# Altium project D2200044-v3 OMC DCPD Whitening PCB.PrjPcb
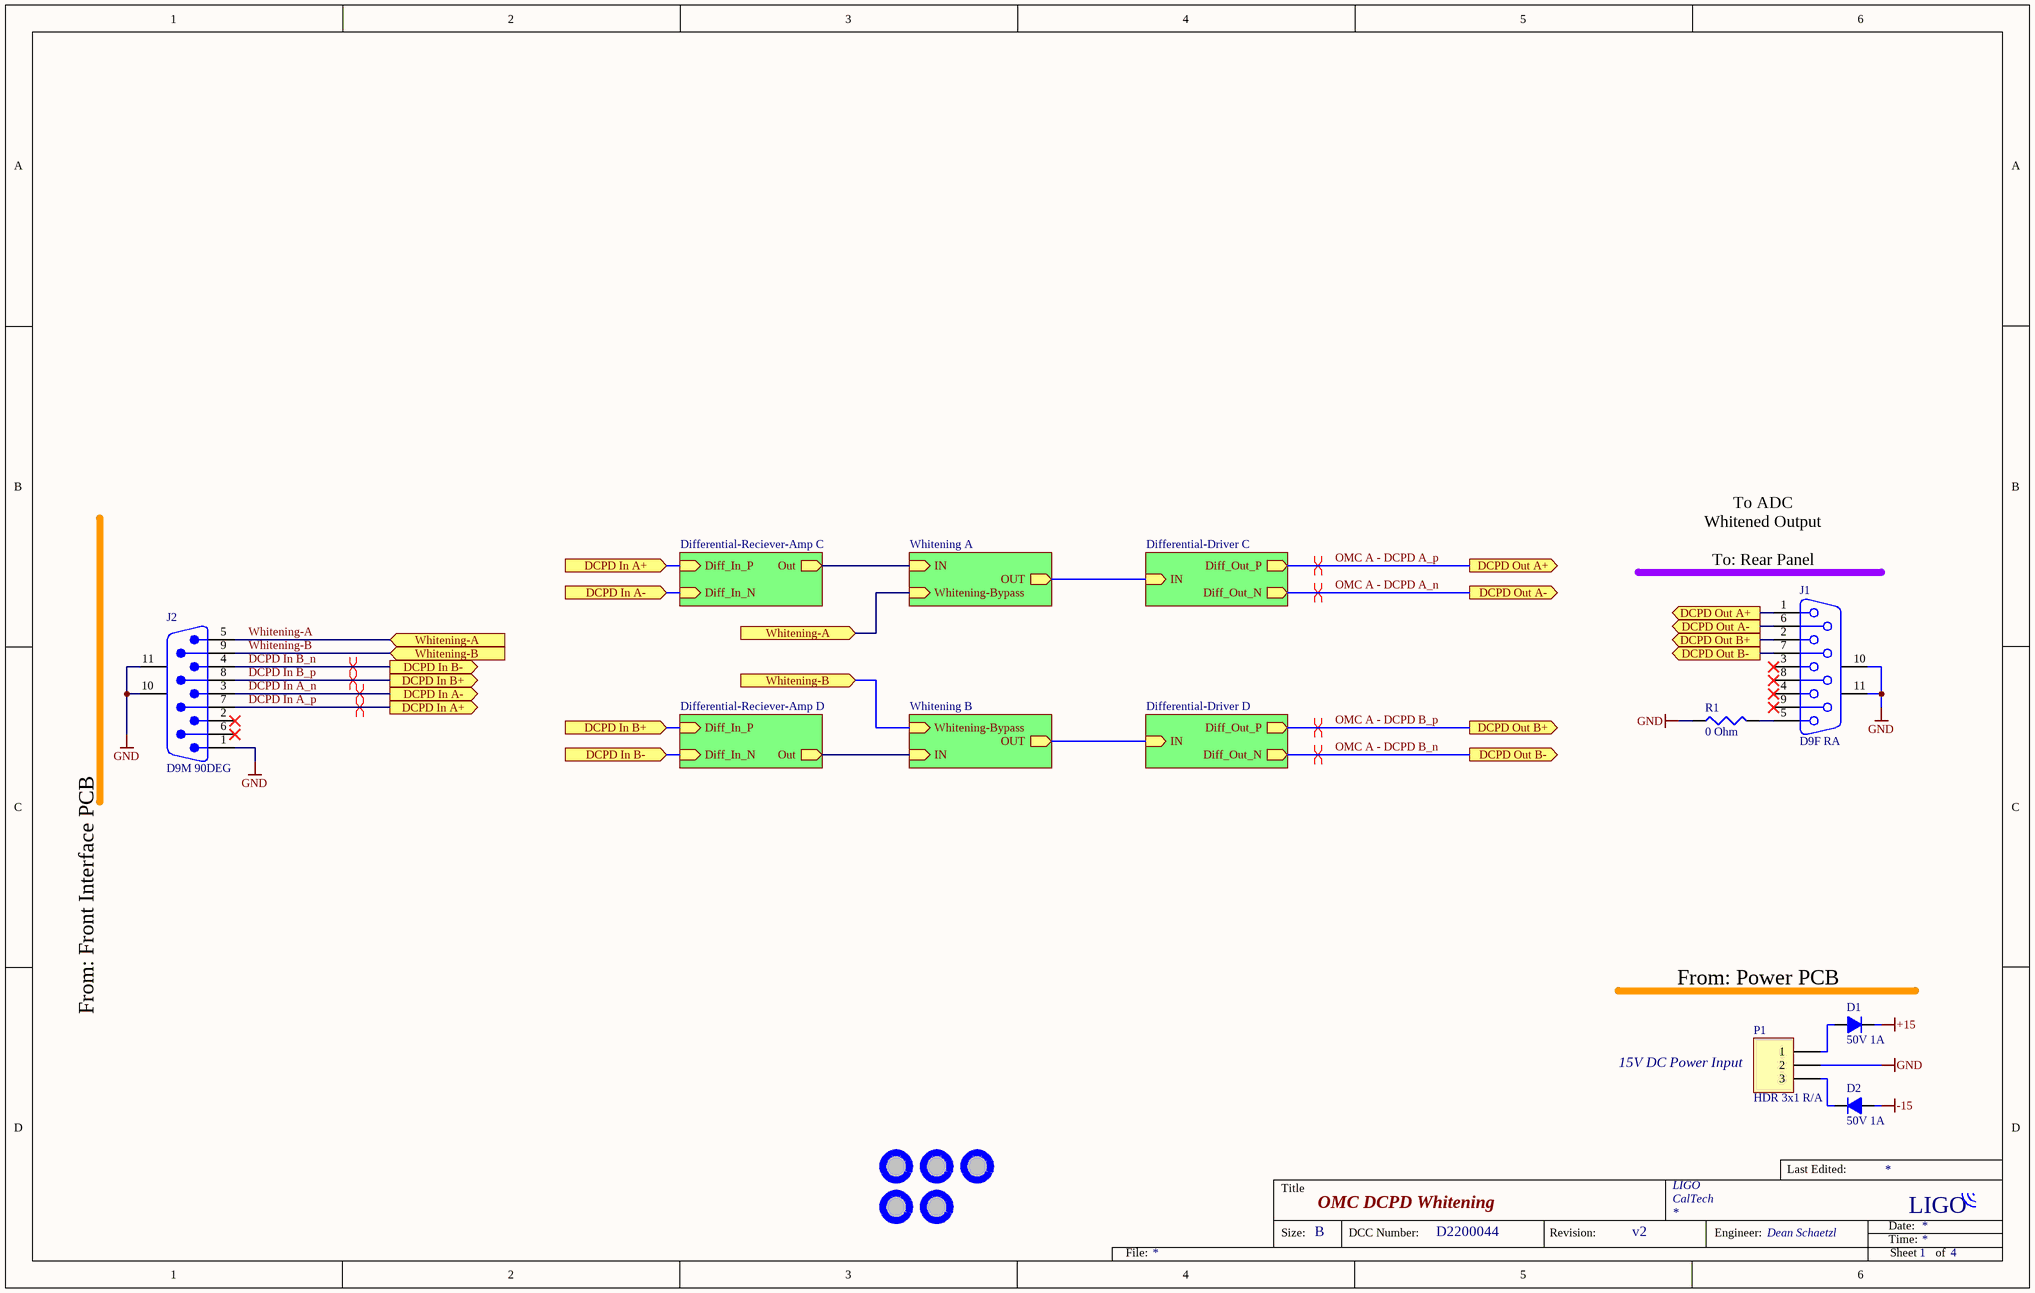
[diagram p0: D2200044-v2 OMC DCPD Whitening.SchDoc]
4 sheets, 95 parts. Net scope: hierarchical (ports join the sheet entries above them; power ports are global).
Board file: D2200044-v3 OMC DCPD Whitening PCB.PcbDoc
Sheets:
  D2200044-v2 OMC DCPD Whitening.SchDoc
    Differential-Reciever-Amp C = Differential-Reciever-Amp.SchDoc
    Differential-Driver C = Differential-Driver.SchDoc
    Differential-Reciever-Amp D = Differential-Reciever-Amp.SchDoc
    Differential-Driver D = Differential-Driver.SchDoc
    Whitening A = Whitening-v3.SchDoc
    Whitening B = Whitening-v3.SchDoc

## Sheet D2200044-v2 OMC DCPD Whitening.SchDoc: OMC DCPD Whitening
size B; CompanyName: LIGO; DrawnBy: Dean Schaetzl; Engineer: Dean Schaetzl; Organization: LIGO; Address1: CalTech; DocumentNumber: D2200044; Revision: v2; SheetNumber: 1; SheetTotal: 4

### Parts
D1  50V 1A  [DO-214AA, SMB]
D2  50V 1A  [DO-214AA, SMB]
J1  D9F RA  [D9F 90DEG]
J2  D9M 90DEG  [D9M 90DEG]
MH1  Mounting Hole #6  [Mounting Hole #6]  (value not drawn)
MH2  Mounting Hole #6  [Mounting Hole #6]  (value not drawn)
MH3  Mounting Hole #6  [Mounting Hole #6]  (value not drawn)
MH4  Mounting Hole #6  [Mounting Hole #6]  (value not drawn)
MH5  Mounting Hole #6  [Mounting Hole #6]  (value not drawn)
P1  HDR 3x1 R/A  [MOLEX HDR1X3 R/A]
R1  0 Ohm  [1206 Resistor]

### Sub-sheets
Differential-Driver C = Differential-Driver.SchDoc: Diff_Out_N (out), Diff_Out_P (out), IN (in)
Differential-Driver D = Differential-Driver.SchDoc: Diff_Out_N (out), Diff_Out_P (out), IN (in)
Differential-Reciever-Amp C = Differential-Reciever-Amp.SchDoc: Diff_In_P (in), Diff_In_N (in), Out (out)
Differential-Reciever-Amp D = Differential-Reciever-Amp.SchDoc: Diff_In_P (in), Diff_In_N (in), Out (out)
Whitening A = Whitening-v3.SchDoc: IN (in), OUT (out), Whitening-Bypass (in)
Whitening B = Whitening-v3.SchDoc: IN (in), OUT (out), Whitening-Bypass (in)

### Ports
DCPD In A+ (in), DCPD In A+ (out), DCPD In A- (in), DCPD In A- (out), DCPD In B+ (in), DCPD In B+ (out), DCPD In B- (in), DCPD In B- (out), DCPD Out A+ (out), DCPD Out A- (out), DCPD Out B+ (out), DCPD Out B- (out), Whitening-A (in), Whitening-B (in)

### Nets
+15: D1.2(K)
-15: D2.1(A)
GND: J1.10(MH1) J1.11(MH2) J2.1 J2.10(MH1) J2.11(MH2) P1.2 R1.1
DCPD In A_n: J2.3 ; port DCPD In A-, sheet Differential-Reciever-Amp C/Diff_In_N
DCPD In A_p: J2.7 ; port DCPD In A+, sheet Differential-Reciever-Amp C/Diff_In_P
DCPD In B_n: J2.4 ; port DCPD In B-, sheet Differential-Reciever-Amp D/Diff_In_N
DCPD In B_p: J2.8 ; port DCPD In B+, sheet Differential-Reciever-Amp D/Diff_In_P
OMC A - DCPD A_n: J1.6 ; port DCPD Out A-, sheet Differential-Driver C/Diff_Out_N
OMC A - DCPD A_p: J1.1 ; port DCPD Out A+, sheet Differential-Driver C/Diff_Out_P
OMC A - DCPD B_n: J1.7 ; port DCPD Out B-, sheet Differential-Driver D/Diff_Out_N
OMC A - DCPD B_p: J1.2 ; port DCPD Out B+, sheet Differential-Driver D/Diff_Out_P
Whitening-A: J2.5 ; port Whitening-A, sheet Whitening A/Whitening-Bypass
Whitening-B: J2.9 ; port Whitening-B, sheet Whitening B/Whitening-Bypass
NetC13A_2: sheet Differential-Reciever-Amp C/Out, sheet Whitening A/IN
NetC13B_2: sheet Differential-Reciever-Amp D/Out, sheet Whitening B/IN
NetD1_1: D1.1(A) P1.1
NetD2_2: D2.2(K) P1.3
NetJ1_5: J1.5 R1.2
NetK1A_8: sheet Differential-Driver C/IN, sheet Whitening A/OUT
NetK1B_8: sheet Differential-Driver D/IN, sheet Whitening B/OUT

Not connected (* = marked no-connect by the designer): J1 3* 4* 8* 9*; J2 2* 6*

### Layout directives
differential pair: DCPD In A_n, DCPD In A_p, DCPD In B_n, DCPD In B_p, OMC A - DCPD A_n, OMC A - DCPD A_p, OMC A - DCPD B_n, OMC A - DCPD B_p

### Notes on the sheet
- (near J1) To ADC
  Whitened Output
  To: Rear Panel
- From: Front Interface PCB
- (near D1) From: Power PCB
- (near P1) 15V DC Power Input

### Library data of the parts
D1 D2 = Diode 50V 1A SMB: DIODE GEN PURP 50V 1A SMB; Manufacturer: Diodes; Manufacturer Part Number: S1AB-13-F; Max Surge Current: 30A; Recovery Time: 1.8us; Forward Voltage: 1.1V; Peak Reverse Current: 5uA; Element Configuration: Single; Polarity: Standard; Capacitance: 10pF
J1 = D9F 90DEG: 9 Position D-Sub Receptacle, Female Sockets Connector; Manufacturer: TE Connectivity; Manufacturer Part Number: 5747844-4; Plating: Tin; Body Material: Metal; Voltage Rating: 125V; Current Rating: 6A; Number of Positions: 9; Number of Ports: 1; Mating Connector Lock: Yes (With); PCB Mount Retention: With; PCB Mounting Orientation: Right Angle; Preloaded: Yes; Sealable: No (Without); Pitch: 0.108inch; PCB Thickness: 1.58mm; Contact Post Length: 0.125inch; Hole Diameter: 3.18mm; Approvals: CSA,UL
J2 = D9M 90DEG: 9 Position D-Sub Plug, Male Pins Connector; Manufacturer: EDAC; Manufacturer Part Number: 621-009-260-042; Body Material: Steel; Current Rating: 5A; Connector Type: D-Sub,Plug; Number of Positions: 9
P1 = MOLEX HDR 3x1 R/A: Connector Header Through Hole, Right Angle 3 position 0.156" (3.96mm); Manufacturer: Molex; Manufacturer Part Number: 0417920512; Contact Resistance: 10mR; Number of Positions: 3; Connector Type: Male Pin
R1 = 0 Ohm (1206): RES 0 OHM JUMPER 1/4W 1206; Manufacturer: Stackpole Electronics; Manufacturer Part Number: RMCF1206ZT0R00; Current Rating: 2A; Working Voltage: 200V; Resistance: 0mR; Power Rating: 250mW

## Sheet Differential-Reciever-Amp.SchDoc: Differential Reciever Amp
size A; Engineer: Dean Schaetzl; Organization: LIGO; Address1: Caltech; DocumentNumber: D2200044; Revision: v1; SheetNumber: 3; SheetTotal: 4
Used 2 times, as channels Differential-Reciever-Amp C, Differential-Reciever-Amp D. Parts and nets are listed once, with the designators drawn on the sheet.
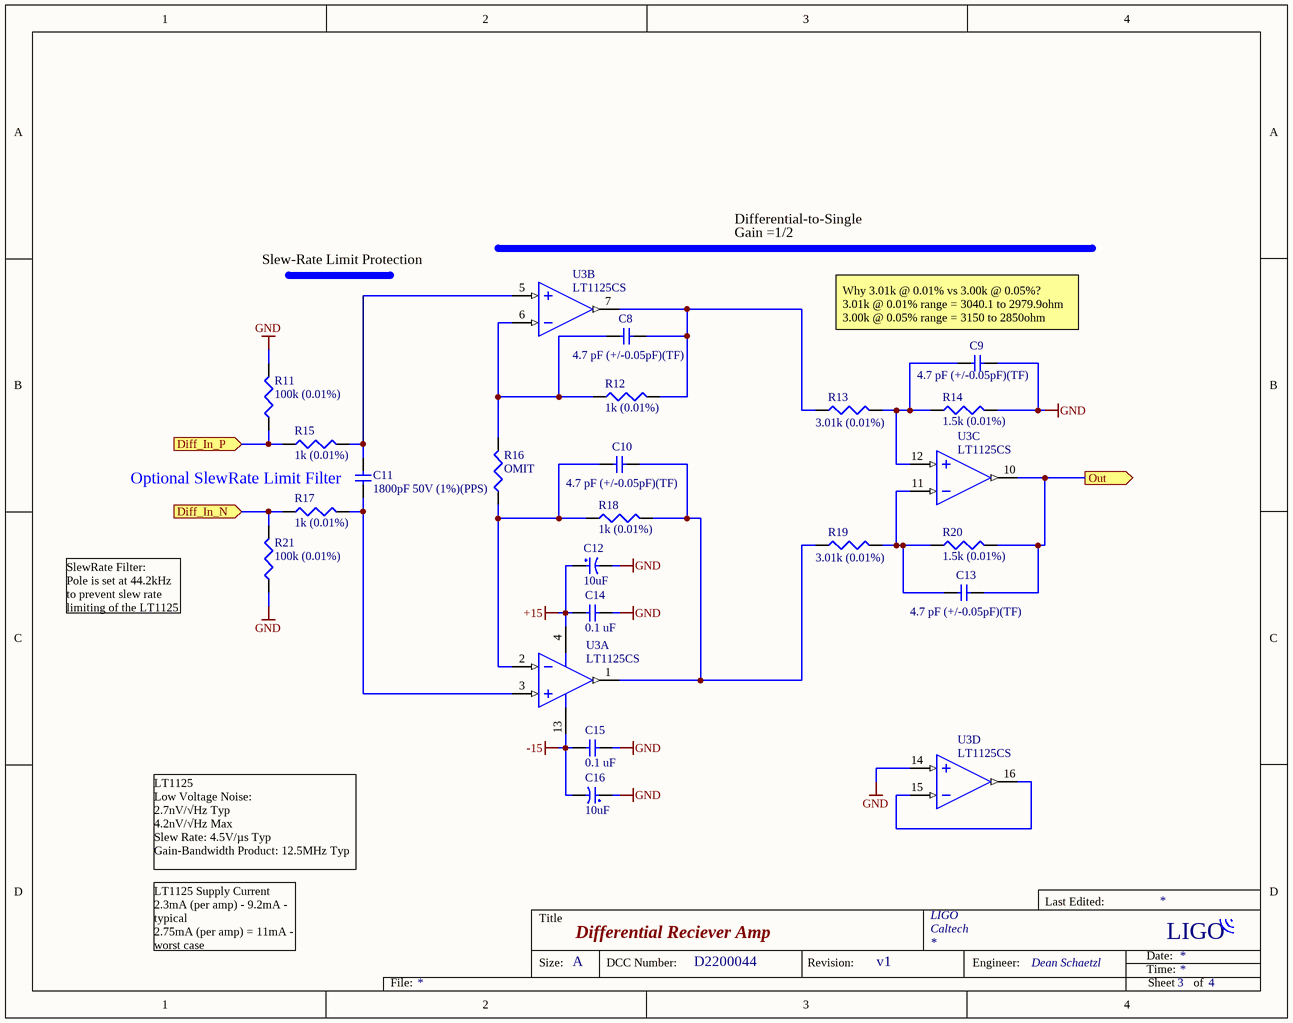
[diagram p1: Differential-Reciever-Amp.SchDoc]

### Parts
C8  4.7 pF (+/-0.05pF)(TF)  [0603 CAP]
C9  4.7 pF (+/-0.05pF)(TF)  [0603 CAP]
C10  4.7 pF (+/-0.05pF)(TF)  [0603 CAP]
C11  1800pF 50V (1%)(PPS)  [0805 CAP]
C12  10uF  [2917 (7343 Metric)]
C13  4.7 pF (+/-0.05pF)(TF)  [0603 CAP]
C14  0.1 uF  [1206 (3216 Metric) CAP]
C15  0.1 uF  [1206 (3216 Metric) CAP]
C16  10uF  [2917 (7343 Metric)]
R11  100k (0.01%)  [1206 Resistor]
R12  1k (0.01%)  [1206 Resistor]
R13  3.01k (0.01%)  [1206 Resistor]
R14  1.5k (0.01%)  [1206 Resistor]
R15  1k (0.01%)  [1206 Resistor]
R16  OMIT  [1206 Resistor - OMIT]
R17  1k (0.01%)  [1206 Resistor]
R18  1k (0.01%)  [1206 Resistor]
R19  3.01k (0.01%)  [1206 Resistor]
R20  1.5k (0.01%)  [1206 Resistor]
R21  100k (0.01%)  [1206 Resistor]
U3  LT1125CS  [SOIC-16W (0.295", 7.50mm Width)]  (parts A,B,C,D of 4)

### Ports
Diff_In_N (in), Diff_In_P (in), Out (out)

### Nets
+15: C12.1 C14.1 U3.4(V+)
-15: C15.1 C16.2 U3.13(V-)
GND: C9.2 C12.2 C14.2 C15.2 C16.1 R11.2 R14.2 R21.1 U3.14(IN+)
Diff_In_N: R17.1 R21.2 ; port Diff_In_N
Diff_In_P: R11.1 R15.1 ; port Diff_In_P
Out: C13.2 R20.2 U3.10(OUT) ; port Out
NetC8_1: C8.1 R12.1 R16.2 U3.6(IN-)
NetC8_2: C8.2 R12.2 R13.1 U3.7(OUT)
NetC9_1: C9.1 R13.2 R14.1 U3.12(IN+)
NetC10_1: C10.1 R16.1 R18.1 U3.2(IN-)
NetC10_2: C10.2 R18.2 R19.1 U3.1(OUT)
NetC11_1: C11.1 R17.2 U3.3(IN+)
NetC11_2: C11.2 R15.2 U3.5(IN+)
NetC13_1: C13.1 R19.2 R20.1 U3.11(IN-)
NetU3_15: U3.15(IN-) U3.16(OUT)

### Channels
Differential-Reciever-Amp C: designators end in A; ports Diff_In_N=DCPD In A_n Diff_In_P=DCPD In A_p Out=NetC13A_2
Differential-Reciever-Amp D: designators end in B; ports Diff_In_N=DCPD In B_n Diff_In_P=DCPD In B_p Out=NetC13B_2

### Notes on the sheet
- Differential-to-Single
- Gain =1/2
- Slew-Rate Limit Protection
- (near C9) Why 3.01k @ 0.01% vs 3.00k @ 0.05%?
  3.01k @ 0.01% range = 3040.1 to 2979.9ohm
  3.00k @ 0.05% range = 3150 to 2850ohm
- Optional SlewRate Limit Filter
- SlewRate Filter:
  Pole is set at 44.2kHz to prevent slew rate limiting of the LT1125
- LT1125
  Low Voltage Noise:
  2.7nV/√Hz Typ
  4.2nV/√Hz Max
  Slew Rate: 4.5V/µs Typ
  Gain-Bandwidth Product: 12.5MHz Typ
- LT1125 Supply Current
  2.3mA (per amp) - 9.2mA - typical
  2.75mA (per amp) = 11mA - worst case

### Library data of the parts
C8-C10 C13 = 4.7 pF +/- 0.05pF (0603): SMD Microwave Thin-Film Chip Capacitors 0603 4.7pF 50volts C0G +/-0.05pF; Manufacturer: Kyocera AVX; Manufacturer Part Number: 06035J4R7ABTTR; Voltage Rating: 50V
C11 = 1800 pF 50V 1% (0805) PPS Film: Capacitor; ECHU, SMD, Stack Met PPS Film Cap, 50VDC, 0.0018uF, 2%, 0805, Cut Tape; Manufacturer: Panasonic; Manufacturer Part Number: ECH-U1H182GX5; Dielectric Material: Polyphenylene; Capacitance: 1.8nF; Life (Hours): 500Hour; Dissipation Factor: 0.6%; Insulation Resistance: 3GR
C12 C16 = 10uF Tant 10% 35V (2917): 10µF Molded Tantalum Capacitors 35V 2917 (7343 Metric) 125mOhm; Manufacturer: KEMET; Manufacturer Part Number: T495D106K035ATE125; Polarity: Polar; Life (Hours): 2000Hour; Dissipation Factor: 6%; ESR (Equivalent Series Resistance): 125mR; Tolerance: 10%
C14 C15 = 0.1 uF 5% (1206): Multilayer Ceramic Capacitor, C Series, 0.1 - F, - 5%, C0G / NP0, 50 V, 1210 [3225 Metric] ;RoHS Compliant: Yes; Manufacturer: KEMET; Manufacturer Part Number: C1210C104J5GACTU; Capacitance: 100nF; Voltage Rating: 50V; Temperature Coefficient: 30ppm/°C; Dissipation Factor: 0.1%
R11 R21 = 100k Ohm 0.01% (1206): 100 kOhms ±0.01% 0.333W, 1/3W Chip Resistor 1206 (3216 Metric) Anti-Sulfur, Moisture Resistant Thin Film; Manufacturer: Vishay Sfernice; Manufacturer Part Number: P2TC1206D1003LNTA
R12 R15 R17 R18 = 1k Ohm 0.01% (1206): RNCF Precision Thin Film Chip Resistor 1206 Size 1K Ohm 0.01% 0.25 W 5 ppm/°C 2-Pin SMD T/R; Manufacturer: Stackpole Electronics; Manufacturer Part Number: RNCF1206TKY1K00; Resistance: 1kR; Max Power Dissipation: 250mW
R13 R19 = 3.01k Ohm 0.01% (1206): 1206 Thin Film Chip Resistor / 1206 SMD Resistor 0.05% 10PPM 3.01 Kohm; Manufacturer: Panasonic; Manufacturer Part Number: ERA-8ARW3011V; Resistance: 3.01kR; Max Power Dissipation: 250mW; Temperature Coefficient: 10ppm/°C
R14 R20 = 1.5k Ohm 0.01% (1206): Thin Film Resistors - SMD 1/4W 1.5K Ohms 0.01% 1206 2ppm; Manufacturer: Susumu; Manufacturer Part Number: RG3216L-152-L-T05; Voltage Rating: 200V; Resistance: 1.5kR; Power Rating: 250mW; Temperature Coefficient: 2ppm/°C; Max Power Dissipation: 125mW
R16 = 1206 Resistor OMIT
U3 = LT1125CS: OP Amp Quad GP ±22V 16-Pin SOIC W; Manufacturer: Analog Devices / Linear Technology; Manufacturer Part Number: LT1125CSW#PBF; Dual Supply Voltage: 9V; Number of Channels: 4; Voltage Gain: 143.52dB; Gain Bandwidth Product: 12.5MHz; Input Bias Current: 30nA; Common Mode Rejection Ratio: 106dB; Input Offset Voltage (Vos): 140uV; Operating Supply Current: 2.3mA; Slew Rate: 4.5V/µs; Power Supply Rejection Ratio (PSRR): 110dB; Min Dual Supply Voltage: 4V

## Sheet Differential-Driver.SchDoc: Differential Driver
size A; DrawnBy: Dean Schaetzl; Engineer: Dean Schaetzl; Organization: LIGO; DocumentNumber: D2200044; Revision: v1; SheetNumber: 2; SheetTotal: 4
Used 2 times, as channels Differential-Driver C, Differential-Driver D. Parts and nets are listed once, with the designators drawn on the sheet.
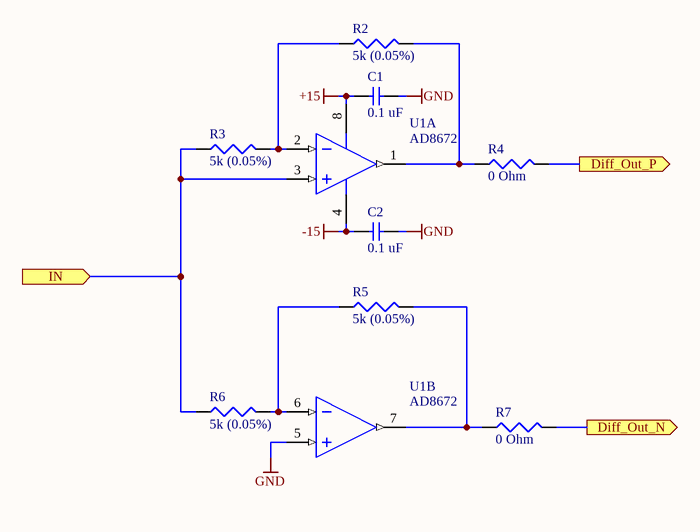
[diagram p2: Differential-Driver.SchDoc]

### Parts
C1  0.1 uF  [1206 (3216 Metric) CAP]
C2  0.1 uF  [1206 (3216 Metric) CAP]
R2  5k (0.05%)  [0805 Resistor]
R3  5k (0.05%)  [0805 Resistor]
R4  0 Ohm  [1206 Resistor]
R5  5k (0.05%)  [0805 Resistor]
R6  5k (0.05%)  [0805 Resistor]
R7  0 Ohm  [1206 Resistor]
U1  AD8672  [SOIC-8 (0.154", 3.90mm Width)]  (parts A,B of 2)

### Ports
Diff_Out_N (out), Diff_Out_P (out), IN (in)

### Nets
+15: C1.1 U1.8(V+)
-15: C2.1 U1.4(V-)
GND: C1.2 C2.2 U1.5(IN+)
Diff_Out_N: R7.2 ; port Diff_Out_N
Diff_Out_P: R4.2 ; port Diff_Out_P
IN: R3.1 R6.1 U1.3(IN+) ; port IN
NetR2_1: R2.1 R3.2 U1.2(IN-)
NetR2_2: R2.2 R4.1 U1.1(OUT)
NetR5_1: R5.1 R6.2 U1.6(IN-)
NetR5_2: R5.2 R7.1 U1.7(OUT)

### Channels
Differential-Driver C: designators end in A; ports Diff_Out_N=OMC A - DCPD A_n Diff_Out_P=OMC A - DCPD A_p IN=NetK1A_8
Differential-Driver D: designators end in B; ports Diff_Out_N=OMC A - DCPD B_n Diff_Out_P=OMC A - DCPD B_p IN=NetK1B_8

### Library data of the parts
C1 C2 = 0.1 uF 5% (1206): as C14 on sheet Differential-Reciever-Amp
R2 R3 R5 R6 = 5k Ohm 0.05% (0805): Res Thin Film 0805 5K Ohm 0.05% 1/4W ±5ppm/°C Molded SMD SMD T/R; Manufacturer: Vishay Dale Thin Film; Manufacturer Part Number: PLT0805Z5001AST5; Resistance: 5kR; Power Rating: 250mW; Voltage Rating: 100V
R4 R7 = 0 Ohm (1206): as R1 on sheet D2200044-v2 OMC DCPD Whitening
U1 = AD8672: IC OPAMP GP 10MHZ 8SOIC; Manufacturer: Analog Devices; Manufacturer Part Number: AD8672ARZ; Common Mode Rejection Ratio: 120dB; Min Supply Voltage: 10V; Max Supply Voltage: 36V; Voltage Gain: 135.56dB; Min Dual Supply Voltage: 5V; Max Dual Supply Voltage: 15V; Slew Rate: 4V/µs; Number of Channels: 2; Input Bias Current: 3nA; Input Offset Voltage (Vos): 75uV; Power Supply Rejection Ratio (PSRR): 130dB; Operating Supply Current: 7mA; Settling Time: 5.1us; Dual Supply Voltage: 9V; Output Current per Channel: 20mA; Input Voltage Noise Density: 2.8nV/sqrt Hz; Quiescent Current: 3.5mA; Input Capacitance: 6.25pF

## Sheet Whitening-v3.SchDoc: Whitening
size A; DrawnBy: D Schaetzl; Engineer: D Schaetzl; Organization: LIGO; Address1: CIT; DocumentNumber: D2200044; Revision: v3; SheetNumber: 3; SheetTotal: 4
Used 2 times, as channels Whitening A, Whitening B. Parts and nets are listed once, with the designators drawn on the sheet.
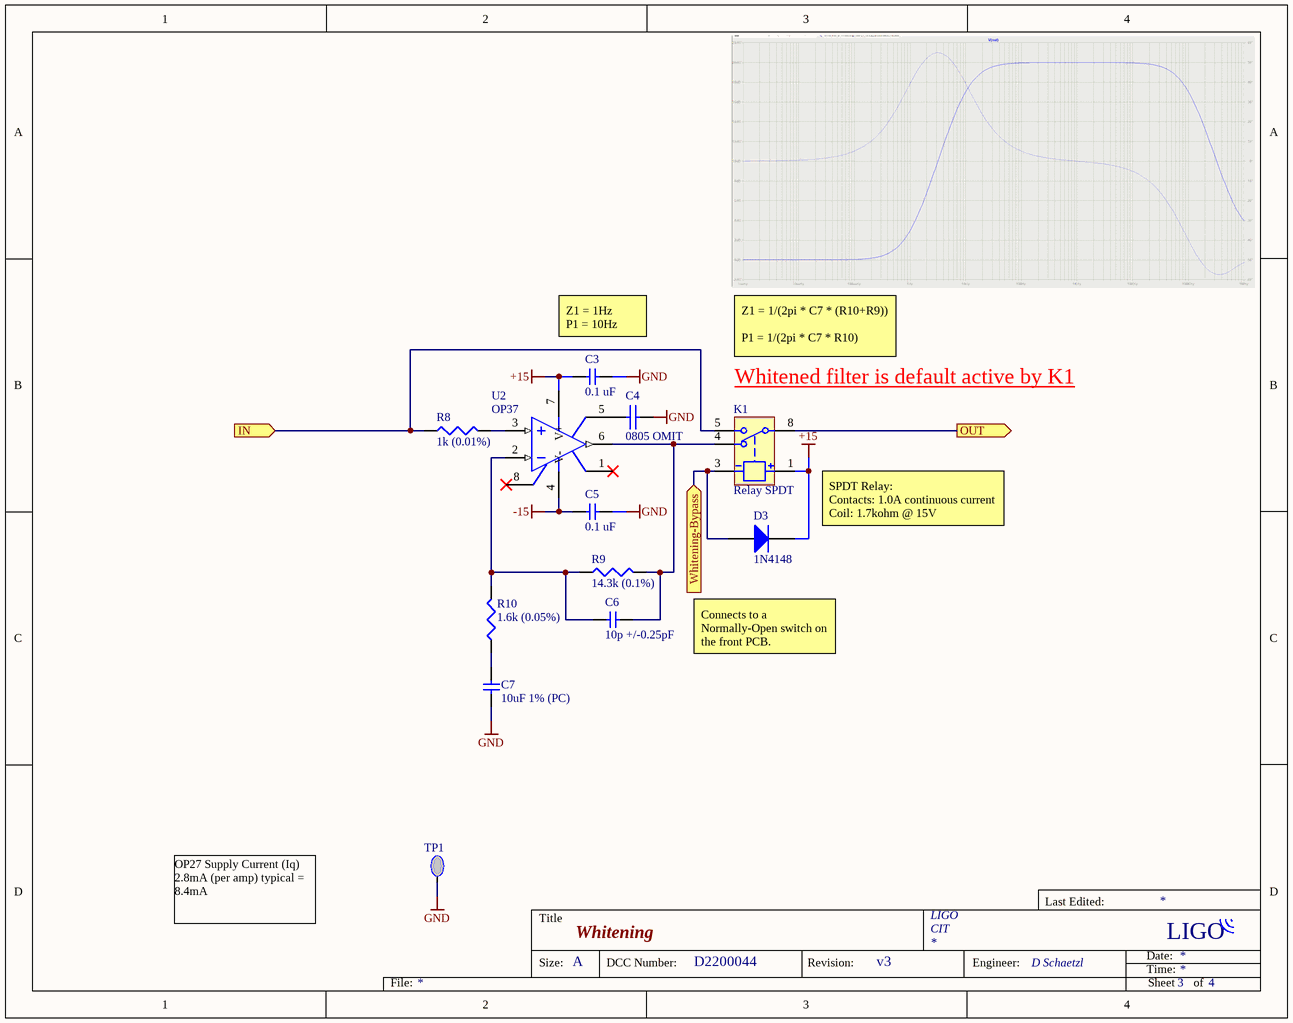
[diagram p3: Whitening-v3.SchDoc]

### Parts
C3  0.1 uF  [1206 (3216 Metric) CAP]
C4  0805 OMIT  [2012[0805] - NF]  (no BOM)
C5  0.1 uF  [1206 (3216 Metric) CAP]
C6  10p +/-0.25pF  [0805 CAP]
C7  10uF 1% (PC)  [CAP Film Axial (Multi Length)]
D3  1N4148  [0402 Diode]
K1  Relay SPDT  [Relay SPDT 0.25A 12V]
R8  1k (0.01%)  [0805 Resistor]
R9  14.3k (0.1%)  [2012[0805]]
R10  1.6k (0.05%)  [0805 Resistor]
TP1  Black  [Test Point Tall - Black]  (value not drawn)
U2  OP37  [SOIC-8 (0.154", 3.90mm Width)]

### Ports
IN (in), OUT (out), Whitening-Bypass (in)

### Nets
+15: C3.1 D3.2(K) K1.1(Coil_+) U2.7(V+)
-15: C5.1 U2.4(V-)
GND: C3.2 C4.2 C5.2 C7.2 TP1.1
IN: K1.5(NO) R8.1 ; port IN
OUT: K1.8(Pole) ; port OUT
Whitening-Bypass: D3.1(A) K1.3(Coil_-) ; port Whitening-Bypass
NetC4_1: C4.1 U2.5(CMPEN)
NetC6_1: C6.1 R9.1 R10.2 U2.2(IN-)
NetC6_2: C6.2 K1.4(NC) R9.2 U2.6(OUT)
NetC7_1: C7.1 R10.1
NetR8_2: R8.2 U2.3(IN+)

Not connected (* = marked no-connect by the designer): U2 1(Offset_Null)* 8(Offset_Null)*

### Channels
Whitening A: designators end in A; ports IN=NetC13A_2 OUT=NetK1A_8 Whitening-Bypass=Whitening-A
Whitening B: designators end in B; ports IN=NetC13B_2 OUT=NetK1B_8 Whitening-Bypass=Whitening-B

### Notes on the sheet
- (near C3) Z1 = 1Hz
  P1 = 10Hz
- Z1 = 1/(2pi * C7 * (R10+R9))
  P1 = 1/(2pi * C7 * R10)
- (near K1) Whitened filter is default active by K1
- SPDT Relay:
  Contacts: 1.0A continuous current
  Coil: 1.7kohm @ 15V
- Connects to a Normally-Open switch on the front PCB.
- OP27 Supply Current (Iq)
  2.8mA (per amp) typical = 8.4mA

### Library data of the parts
C3 C5 = 0.1 uF 5% (1206): as C14 on sheet Differential-Reciever-Amp
C6 = 10pF 50V +/-0.25pF (0805): Cap Ceramic 10pF 50V C0G 0.25pF SMD 0805 125°C Paper T/R; Manufacturer: KEMET; Manufacturer Part Number: C0805C100C5GAC7800
C7 = 10uF 50V 1% (PC): Metallized Polycarbonate Wrap and Fill Tubular Configuration
D3 = Diode 1N4148 0402: Diode Standard 100V 150mA Surface Mount DFN1006-2; Manufacturer: MCC; Manufacturer Part Number: 1N4148WL2-TP; Reverse Recovery Time: 4ns
K1 = Relay SPDT 12V 0.25A: RELAY REED SPDT .25A 12V; Manufacturer: Comus; Manufacturer Part Number: BFM-1C-12E; Coil Type: Non-Latching; Coil Current: 8mA; Contact Current Rating: 250mA; Operate Time: 1ms; Release Time: 2ms; Coil Power: 96mW; Coil Resistance: 1.5kR
R8 = 1k Ohm 0.01% (0805) 1/8W: RNCF Precision Thin Film Chip Resistor 0805 Size 1K Ohm 0.01% 0.125 W 5 ppm/°C 2-Pin SMD T/R; Manufacturer: Stackpole Electronics; Manufacturer Part Number: RNCF0805TKY1K00; Resistance: 1kR; Max Power Dissipation: 125mW
R9 = 14.3k Ohm 0.1% (0805): RES 14.3 KOHMS 0.1% 1/5W 0805; Manufacturer: TE Connectivity; Manufacturer Part Number: RQ73C2A14K3BTD
R10 = 1.6k Ohm 0.05% (0805): Res Thin Film 0805 1.6K Ohm 0.05% 1/8W ±10ppm/°C Molded SMD SMD Punched Carrier T/R; Manufacturer: Panasonic; Manufacturer Part Number: ERA-6ARW162V; Resistance: 1.6kR; Power Rating: 125mW; Voltage Rating: 100V
TP1 = TPT - Black: Black PC Test Point, Multipurpose Phosphor Bronze Silver Plating 0.063" (1.60mm) Hole Diameter Mounting Type; Manufacturer: Keystone Electronics; Manufacturer Part Number: 5011; Body Material: PBT; Gender: Female; Number of Ports: 1; Inside Diameter: 1.78mm; Hole Diameter: 1.6mm
U2 = OP37GSZ-REEL: Op Amp Single Precision Amplifier ±22V 8-Pin SOIC N T/R; Manufacturer: Analog Devices; Voltage Gain: 123.52dB; Unity Gain Bandwidth Product: 63MHz; Common Mode Rejection Ratio: 114dB; Min Dual Supply Voltage: 4V; Slew Rate: 17V/µs; Number of Circuits: 1; Input Bias Current: 15nA; Input Offset Voltage (Vos): 30uV; Input Voltage Noise Density: 3.8nV/sqrt Hz; Quiescent Current: 5.67mA; Amplifier Type: GENERAL PURPOSE

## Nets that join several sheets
+15: D2200044-v2 OMC DCPD Whitening (D1.2), Differential-Reciever-Amp C (C12A.1 C14A.1 U3A.4), Differential-Driver C (C1A.1 U1A.8), Differential-Reciever-Amp D (C12B.1 C14B.1 U3B.4), Differential-Driver D (C1B.1 U1B.8), Whitening A (C3A.1 D3A.2 K1A.1 U2A.7), Whitening B (C3B.1 D3B.2 K1B.1 U2B.7)
-15: D2200044-v2 OMC DCPD Whitening (D2.1), Differential-Reciever-Amp C (C15A.1 C16A.2 U3A.13), Differential-Driver C (C2A.1 U1A.4), Differential-Reciever-Amp D (C15B.1 C16B.2 U3B.13), Differential-Driver D (C2B.1 U1B.4), Whitening A (C5A.1 U2A.4), Whitening B (C5B.1 U2B.4)
GND: D2200044-v2 OMC DCPD Whitening (7 pins), Differential-Reciever-Amp C (9 pins), Differential-Driver C (C1A.2 C2A.2 U1A.5), Differential-Reciever-Amp D (9 pins), Differential-Driver D (C1B.2 C2B.2 U1B.5), Whitening A (5 pins), Whitening B (5 pins)
DCPD In A_n: D2200044-v2 OMC DCPD Whitening (J2.3), Differential-Reciever-Amp C (R17A.1 R21A.2)
DCPD In A_p: D2200044-v2 OMC DCPD Whitening (J2.7), Differential-Reciever-Amp C (R11A.1 R15A.1)
DCPD In B_n: D2200044-v2 OMC DCPD Whitening (J2.4), Differential-Reciever-Amp D (R17B.1 R21B.2)
DCPD In B_p: D2200044-v2 OMC DCPD Whitening (J2.8), Differential-Reciever-Amp D (R11B.1 R15B.1)
NetC13A_2: Differential-Reciever-Amp C (C13A.2 R20A.2 U3A.10), Whitening A (K1A.5 R8A.1)
NetC13B_2: Differential-Reciever-Amp D (C13B.2 R20B.2 U3B.10), Whitening B (K1B.5 R8B.1)
NetK1A_8: Differential-Driver C (R3A.1 R6A.1 U1A.3), Whitening A (K1A.8)
NetK1B_8: Differential-Driver D (R3B.1 R6B.1 U1B.3), Whitening B (K1B.8)
OMC A - DCPD A_n: D2200044-v2 OMC DCPD Whitening (J1.6), Differential-Driver C (R7A.2)
OMC A - DCPD A_p: D2200044-v2 OMC DCPD Whitening (J1.1), Differential-Driver C (R4A.2)
OMC A - DCPD B_n: D2200044-v2 OMC DCPD Whitening (J1.7), Differential-Driver D (R7B.2)
OMC A - DCPD B_p: D2200044-v2 OMC DCPD Whitening (J1.2), Differential-Driver D (R4B.2)
Whitening-A: D2200044-v2 OMC DCPD Whitening (J2.5), Whitening A (D3A.1 K1A.3)
Whitening-B: D2200044-v2 OMC DCPD Whitening (J2.9), Whitening B (D3B.1 K1B.3)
